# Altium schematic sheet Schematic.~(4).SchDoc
size A4; SheetNumber: 1; SheetTotal: 1
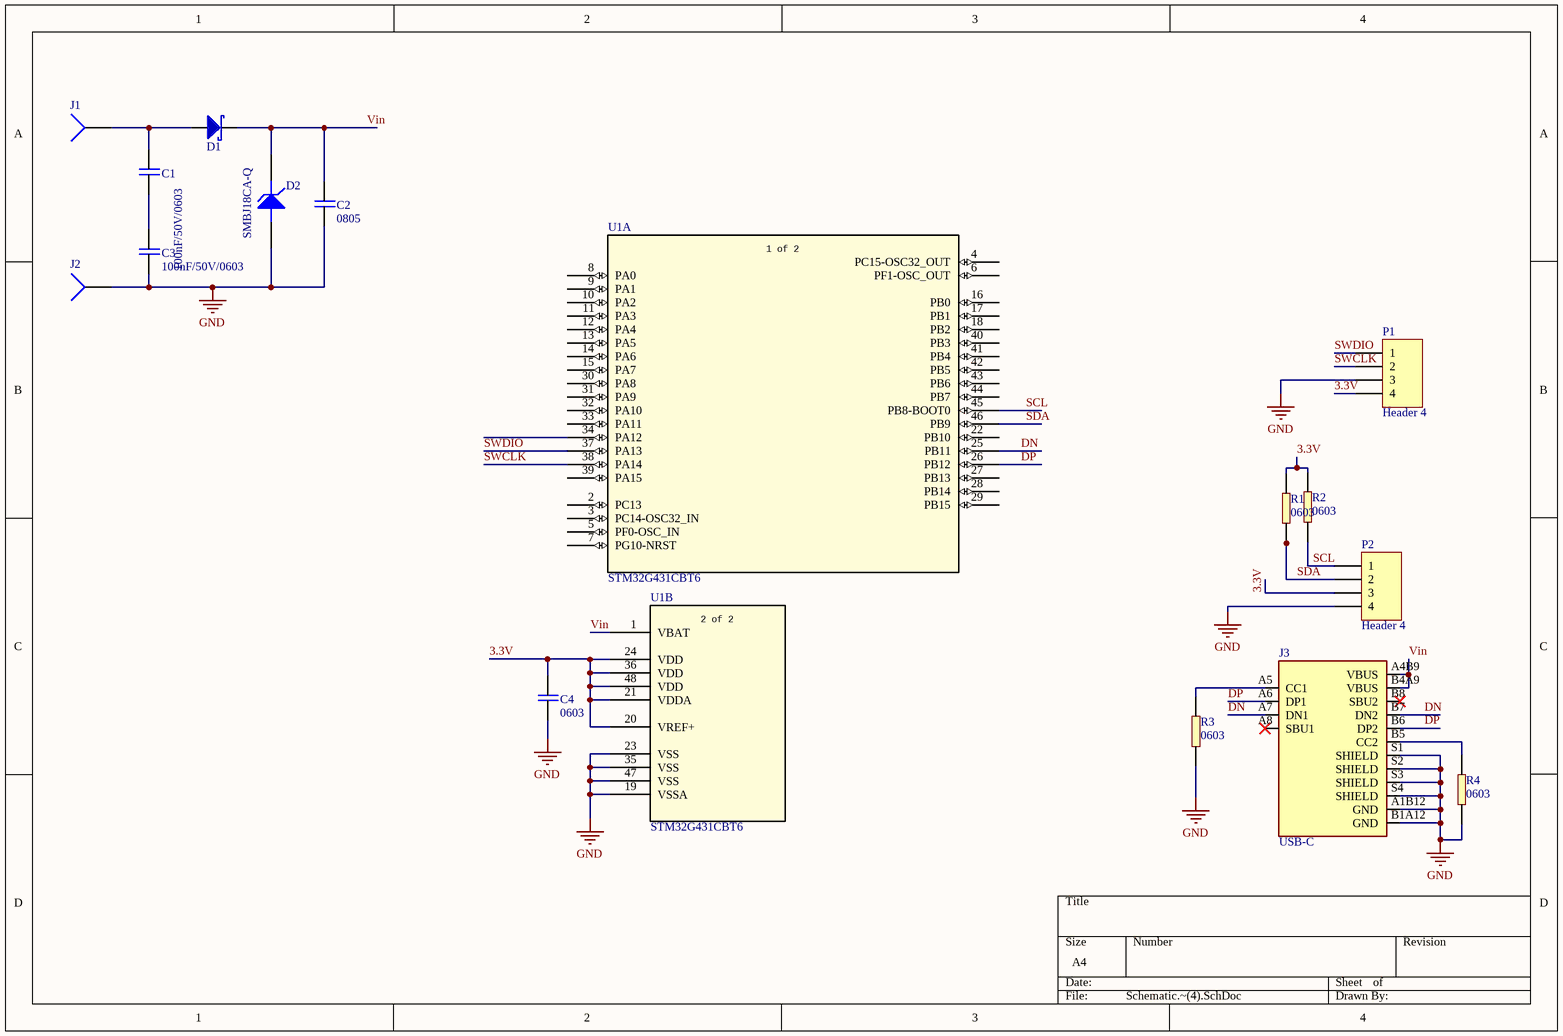
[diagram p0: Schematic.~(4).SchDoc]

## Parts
C1  100nF/50V/0603  [C0603]
C2  0805  [C0805]
C3  100nF/50V/0603  [C0603]
C4  0603  [C0603]
D1  RB058LAM-60TF  (value not drawn)
D2  SMBJ18CA-Q  [SMBJ18CA-Q]
J1  Socket  [PIN1]  (value not drawn)
J2  Socket  [PIN1]  (value not drawn)
J3  USB-C  [HRO_TYPE-C-31-M-12]
P1  Header 4  [HDR1X4]
P2  Header 4  [HDR1X4]
R1  0603  [R0603]
R2  0603  [R0603]
R3  0603  [R0603]
R4  0603  [R0603]
U1  STM32G431CBT6  [LQFP48-7x7mm]  (parts A,B of 2)

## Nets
GND: C2.1 C3.1 C4.1 D2.A J2.1 J3.A1B12(GND) J3.B1A12(GND) J3.S1(SHIELD) J3.S2(SHIELD) J3.S3(SHIELD) J3.S4(SHIELD) P1.3 P2.4 R3.1 R4.1 U1.19(VSSA) U1.23(VSS) U1.35(VSS) U1.47(VSS)
3.3V: C4.2 P1.4 P2.3 R1.2 R2.2 U1.20(VREF+) U1.21(VDDA) U1.24(VDD) U1.36(VDD) U1.48(VDD)
DN: J3.A7(DN1) J3.B7(DN2) U1.25(PB11)
DP: J3.A6(DP1) J3.B6(DP2) U1.26(PB12)
SCL: P2.1 R2.1 U1.45(PB8-BOOT0)
SDA: P2.2 R1.1 U1.46(PB9)
SWCLK: P1.2 U1.38(PA14)
SWDIO: P1.1 U1.37(PA13)
Vin: C2.2 D1.K D2.K J3.A4B9(VBUS) J3.B4A9(VBUS) U1.1(VBAT)
NetC1_1: C1.1 C3.2
NetC1_2: C1.2 D1.A J1.1
NetJ3_A5: J3.A5(CC1) R3.2
NetJ3_B5: J3.B5(CC2) R4.2

Not connected (* = marked no-connect by the designer): J3 A8(SBU1)* B8(SBU2)*; U1 2(PC13) 3(PC14-OSC32_IN) 4(PC15-OSC32_OUT) 5(PF0-OSC_IN) 6(PF1-OSC_OUT) 7(PG10-NRST) 8(PA0) 9(PA1) 10(PA2) 11(PA3) 12(PA4) 13(PA5) 14(PA6) 15(PA7) 16(PB0) 17(PB1) 18(PB2) 22(PB10) 27(PB13) 28(PB14) 29(PB15) 30(PA8) 31(PA9) 32(PA10) 33(PA11) 34(PA12) 39(PA15) 40(PB3) 41(PB4) 42(PB5) 43(PB6) 44(PB7)

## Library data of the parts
C1 C3 C4 = C0603
C2 = C0805
D1 = RB058LAM-60TF: Schottky Barrier Diode 60V 3A SOD-128
J3 = USB-C: USB-C (USB TYPE-C) USB 3.2 Gen 2 (USB 3.1 Gen 2, Superspeed + (USB 3.1)) Receptacle Connector 24 Position Surface Mount, Through Hole; MF: Adam Technologies
P1 P2 = Header 4: Header, 4-Pin
R1-R4 = R0603
U1 = STM32G431CBT6: Mainstream Arm Cortex-M4 MCU 170 MHz with 128 Kbytes of Flash memory, Math Accelerator, Medium Analog level integration; Manufacturer_Name: STMicroelectronics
